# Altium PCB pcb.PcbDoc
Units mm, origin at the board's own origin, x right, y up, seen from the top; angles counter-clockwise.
Board outline 64.9 x 47.24 mm, 2 copper layers (Top Layer, Bottom Layer); 18 components, 15 nets, 54 pads, 4 vias.
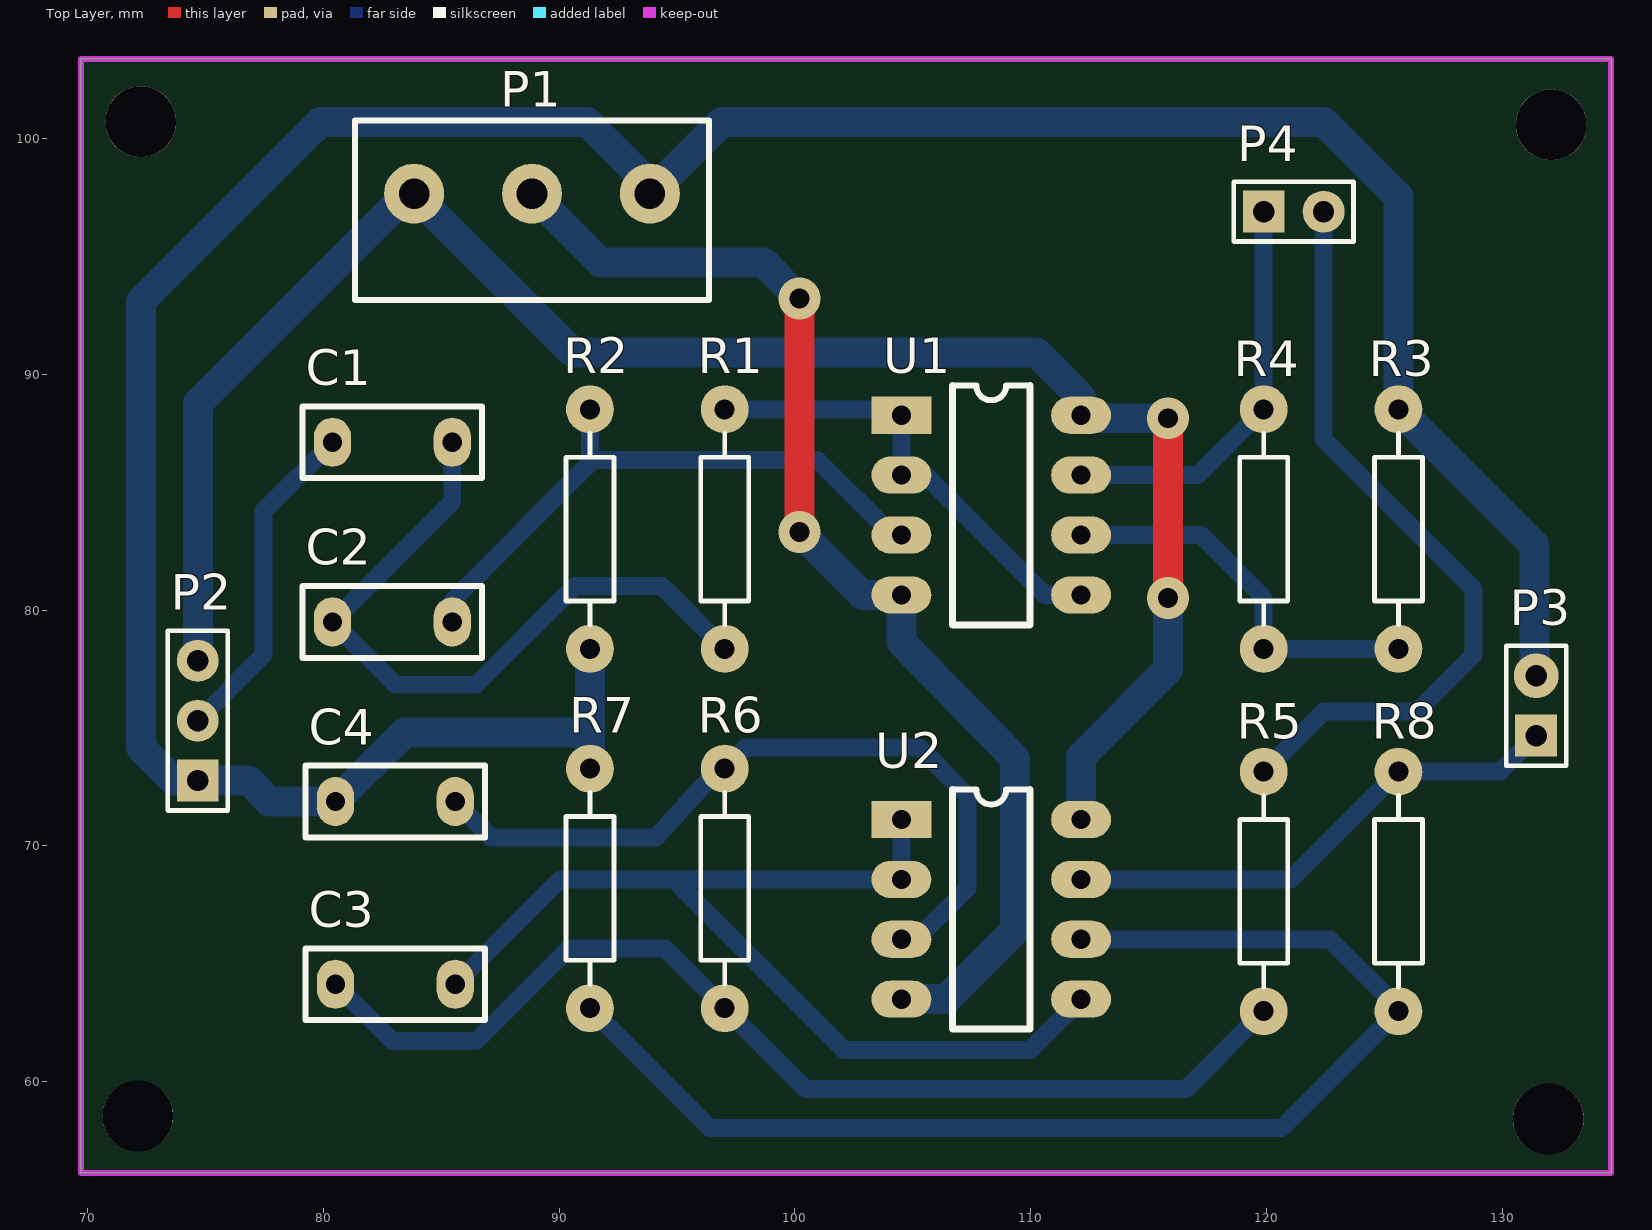
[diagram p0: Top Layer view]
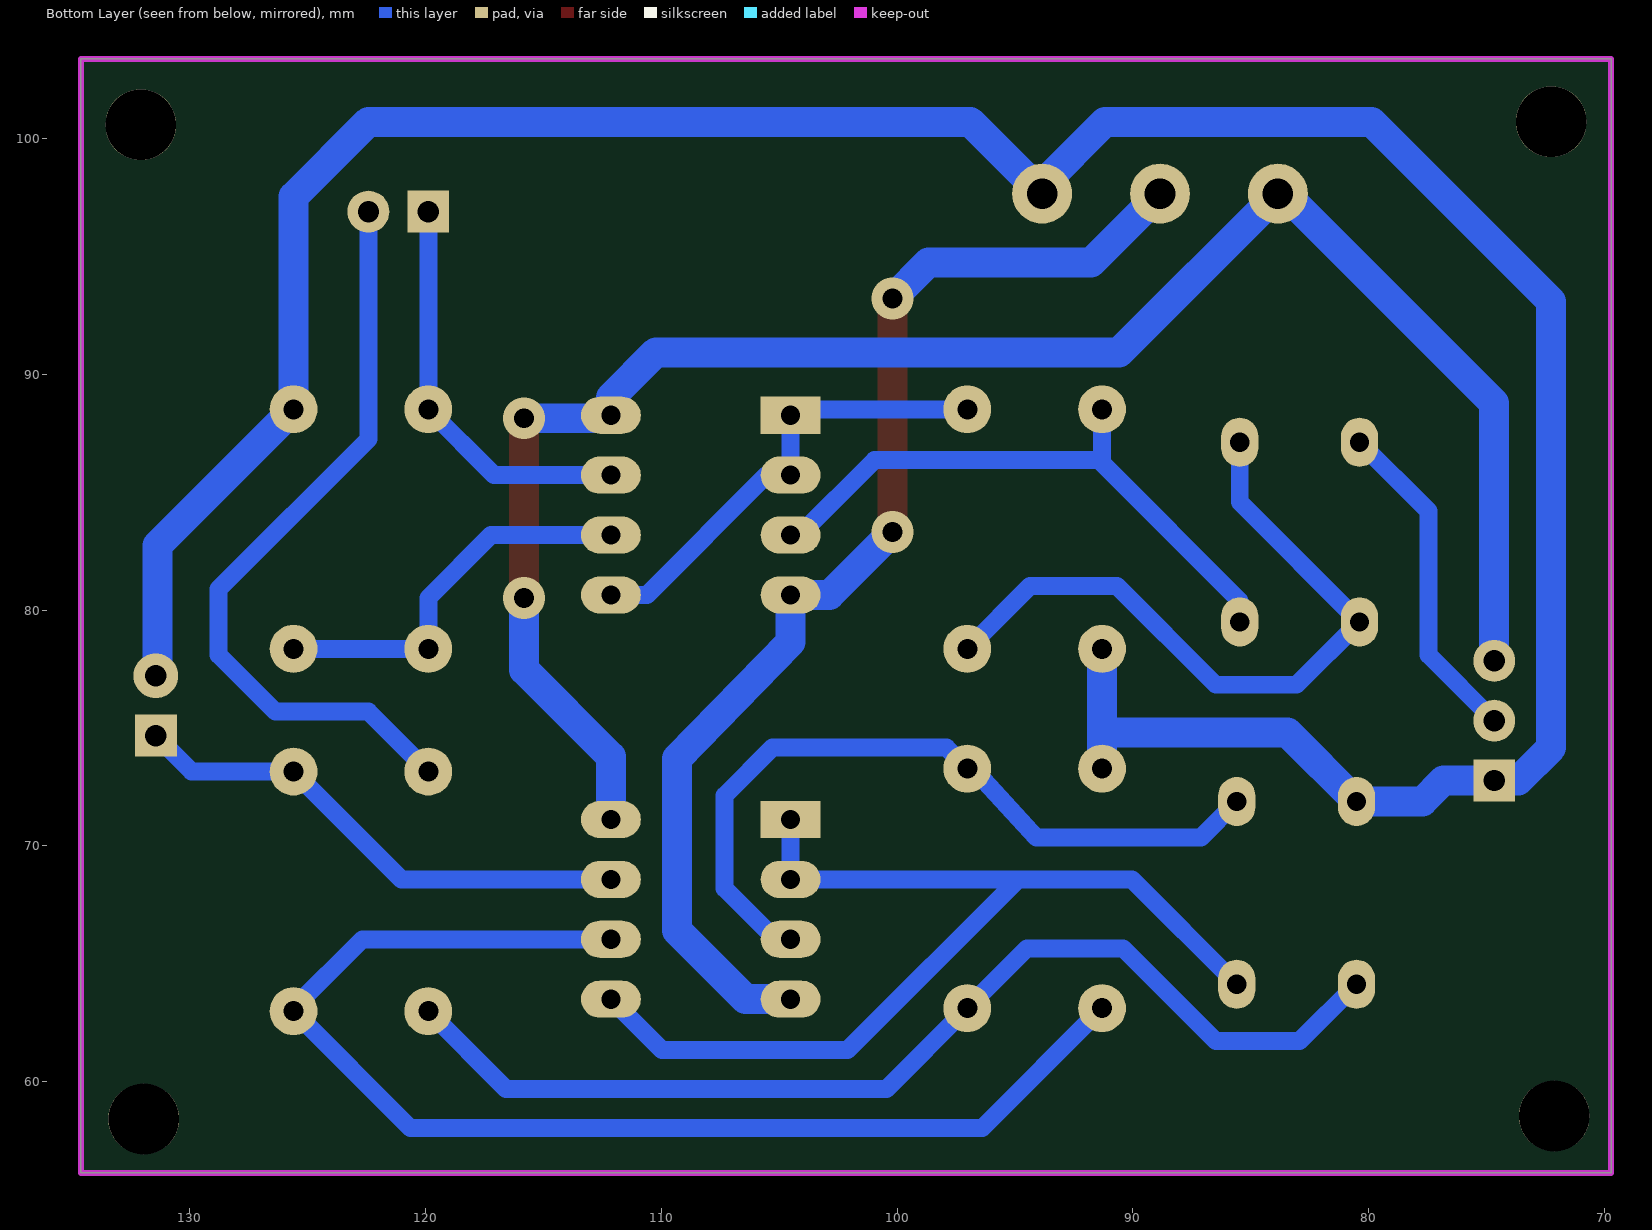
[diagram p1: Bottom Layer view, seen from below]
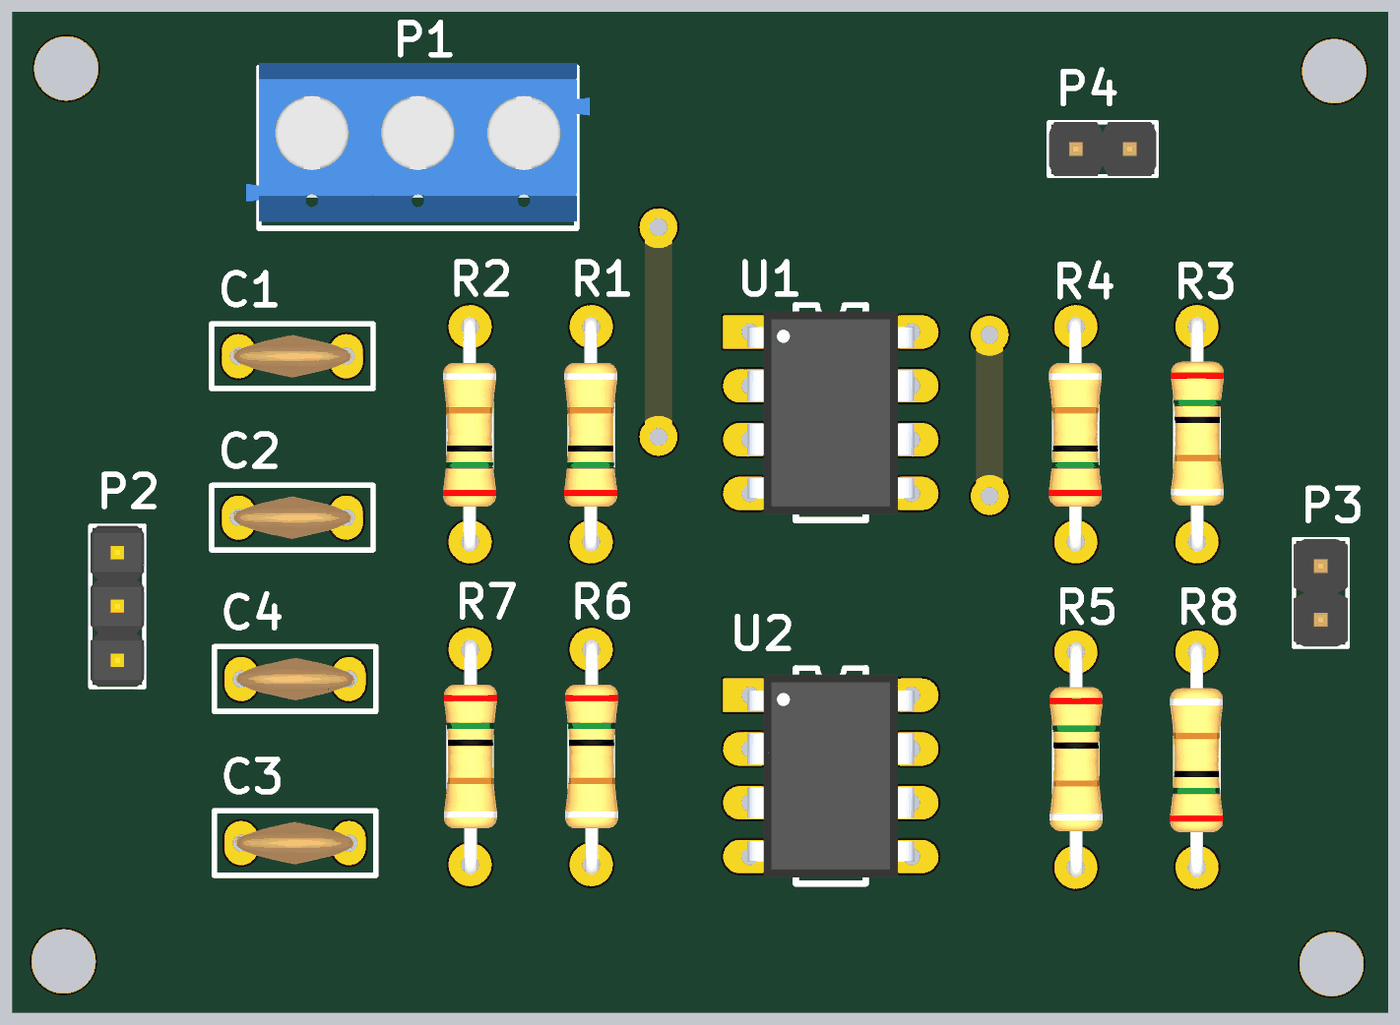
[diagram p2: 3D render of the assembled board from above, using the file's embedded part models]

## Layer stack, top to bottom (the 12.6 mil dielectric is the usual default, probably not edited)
Top Solder: solder mask 0.0102, Solder Resist, Dk 3.5
Top Layer: signal copper 0.0356
Dielectric 1: dielectric 0.32, FR-4, Dk 4.8
Bottom Layer: signal copper 0.0356
Bottom Solder: solder mask 0.0102, Solder Resist, Dk 3.5

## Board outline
69.723,56.134 69.723,103.378 134.62,103.378 134.62,56.134

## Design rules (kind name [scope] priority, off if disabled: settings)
Clearance [All] p1: gap=0.381 ignorepadtopadclearanceinfootprint=FALSE
PolygonConnect [All] p1: connectstyle=Relief reliefconductorwidth=0.254 reliefentries=4 polygonreliefangle="90 Angle" airgapwidth=0.254
RoutingVias [All] p1: holewidth=0.711 width=1.27 viastyle="Through Hole" minholewidth=0.711 minwidth=1.27 maxholewidth=0.711 maxwidth=1.27
SolderMaskExpansion [All] p1: expansion=0.102
Width Width_1 [InNetClass('Power Class')] p1: maxlimit=1.27 minlimit=1.27 preferedwidth=1.27
Width Width_2 [InNetClass('Signal Class')] p2: maxlimit=0.762 minlimit=0.762 preferedwidth=0.762
30 further rules are at their usual default settings.

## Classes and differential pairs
net class "Signal Class": HP_in HP_out LP_in LP_out NetC1_1 NetC2_1 NetC3_1 NetC3_2 NetC4_2 NetR1_1 NetR3_1 NetR7_1
net class "Power Class": -VCC GND VCC
component class Sema_BCG_2: C1 C2 C4 P1 P2 P3 P4 R1 R2 R3 R4 R5 R6 R7 R8 U1 U2

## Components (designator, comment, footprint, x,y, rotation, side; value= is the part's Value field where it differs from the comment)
C1 "Cap" CAP200 85.471,87.122 r180 top value=10uF
C2 "Cap" CAP200 85.471,79.502 r180 top value=10uF
C3 "Cap" CAP200 85.598,64.135 r180 top value=100nF
C4 "Cap" CAP200 80.518,71.882 r0 top value=100nF
P1 "POWER" DG301-5.0 88.853,97.663 r180 top
P2 "Signal IN (ACCEL)" HDR1X3 74.676,75.311 r180 top
P3 "Signal OUT (DAQ)" HDR1X2#1 131.445,74.676 r90 top
P4 "FILT" HDR1X2#2 119.888,96.901 r0 top
R1 "Res1" AXIAL-0.4 97.028,83.439 r270 top value=10K
R2 "Res1" AXIAL-0.4 91.313,83.439 r270 top value=10K
R3 "Res1" AXIAL-0.4 125.603,83.439 r90 top value=2k7
R4 "Res1" AXIAL-0.4 119.888,83.439 r270 top value=47K
R5 "Res1" AXIAL-0.4 119.888,68.072 r90 top value=100K
R6 "Res1" AXIAL-0.4 97.028,68.199 r90 top value=100K
R7 "Res1" AXIAL-0.4 91.313,68.199 r90 top value=47k
R8 "Res1" AXIAL-0.4 125.603,68.072 r270 top value=100k
U1 "TL072" DIP-8 104.521,88.265 r0 top
U2 "TL072" DIP-8 104.521,71.12 r0 top

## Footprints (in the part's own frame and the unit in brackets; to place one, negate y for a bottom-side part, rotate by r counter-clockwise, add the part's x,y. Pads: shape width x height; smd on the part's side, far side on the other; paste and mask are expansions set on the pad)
AXIAL-0.4 [mil] "Axial Device, Thru-Hole; 2 Leads; 0.4 in Pin Spacing"
  round 80 hole 33.46: 1(-200,0) 2(200,0)
  silkscreen extent -160,-40 160,40, body extent -219,-50 219,48, height 146
CAP200 [mil]
  oval 62x82 hole 32: 1(0,0) 2(200,0)
  silkscreen extent -50,-60 250,60, body extent -11,-39 210,39, height 246
DG301-5.0 [mm]
  round 2.54 hole 1.3: 1(-5,0) 2(0,0) 3(5,0)
  silkscreen extent -7.5,-3.1 7.5,4.5, body extent -8.1,-3.3 8.1,4.2, height 5
DIP-8 [mil]
  rect 100x62 hole 32: 1(0,0)
  oval 100x62 hole 32: 2(0,-100) 3(0,-200) 4(0,-300) 5(300,-300) 6(300,-200) 7(300,-100) 8(300,0)
  silkscreen extent 85,-350 215,50, body extent -5,-339 305,39, height 200
HDR1X2#1 [mm] "Connector; Header; 2 Position"
  rect 1.778x1.778 hole 0.9: 1(0,0)
  round 1.905 hole 0.9: 2(2.54,0)
  silkscreen extent -1.27,-1.27 3.81,1.27, body extent -1.27,-1.27 3.81,1.27, height 8.79
HDR1X2#2 [mm] "Connector; Header; 2 Position"
  rect 1.778x1.778 hole 0.9: 1(0,0)
  round 1.778 hole 0.9: 2(2.54,0)
  silkscreen extent -1.27,-1.27 3.81,1.27, body extent -1.27,-1.27 3.81,1.27, height 8.79
HDR1X3 [mil]
  rect 70x70 hole 35.43: 1(0,100)
  round 70 hole 35.43: 2(0,0) 3(0,-100)
  silkscreen extent -50,-150 50,150, body extent -50,-150 50,150, height 374

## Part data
C1 C2 C3 C4: "Capacitor"
P1 P2: library part "Header 3", "Header, 3-Pin"
P3 P4: library part "Header 2", "Header, 2-Pin"
R1 R2 R3 R4 R5 R6 R7 R8: "Resistor"
U1 U2: "Dual standard operational amplifier 8-PDIP 0 to 70", Package="PDIP-8 Texas"

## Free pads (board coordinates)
  round 3 hole 3: 0(72.136,58.547) 0(72.263,100.711) 0(131.953,58.42) 0(132.08,100.584)

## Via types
v1: diameter 1.778, hole 0.838, Top Layer to Bottom Layer, 4 vias

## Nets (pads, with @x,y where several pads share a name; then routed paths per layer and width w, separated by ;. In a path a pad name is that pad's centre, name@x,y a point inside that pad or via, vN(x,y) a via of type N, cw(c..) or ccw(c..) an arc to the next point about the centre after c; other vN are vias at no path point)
-VCC: P1.2 U1.4 U2.4 | length 51.1
  Top Layer w1.27: v1@100.076,83.439 v1(100.203,83.312) v1(100.203,93.218)
  Bottom Layer w1.27: P1.2 91.774,94.742 98.679,94.742 v1(100.203,93.218) v1@100.33,93.091 ; v1(100.203,83.312) 102.87,80.645 U1.4 104.521,78.645 109.347,73.698 109.347,66.421 106.426,63.5 U2.4
GND: C4.1 P1.1 P2.1 P3.2 R2.2 R3.2 R7.2 | length 128.9
  Bottom Layer w1.27: R7.2@91.059,73.533 R7.2 91.313,75.057 ; R2.2 91.313,75.057 ; P3.2@131.381,77.279 131.381,82.74 R3.2 125.603,97.536 122.428,100.711 96.901,100.711 P1.1 93.853,98.044 91.186,100.711 79.883,100.711 72.263,93.091 72.263,74.168 73.66,72.771 P2.1 76.835,72.771 77.724,71.882 C4.1 83.439,74.803 91.059,74.803 91.313,75.057
HP_in: C1.2 P2.2 | length 14.6
  Bottom Layer w0.762: P2.2@75.057,75.311 P2.2 77.47,78.105 77.47,84.201 C1.2
HP_out: P4.1 R4.1 U1.7 | length 17.3
  Bottom Layer w0.762: U1.7 117.094,85.725 R4.1 P4.1
LP_in: P4.2 R5.2 | length 32.4
  Bottom Layer w0.762: R5.2 122.428,75.692 126.365,75.692 128.778,78.105 128.778,80.899 122.428,87.249 P4.2
LP_out: P3.1 R8.1 U2.7 | length 21.8
  Bottom Layer w0.762: U2.7 121.031,68.58 R8.1 129.921,73.152 P3.1
NetC1_1: C1.1 C2.2 R1.2 | length 30.3
  Bottom Layer w0.762: C1.1 85.471,84.582 C2.2 83.058,76.835 86.487,76.835 90.678,81.026 94.361,81.026 R1.2
NetC2_1: C2.1 R2.1 U1.3 | length 26
  Bottom Layer w0.762: C2.1 85.471,80.391 91.313,86.233 ; R2.1 91.313,86.233 ; U1.3 104.14,83.185 100.965,86.36 91.44,86.36 91.313,86.233
NetC3_1: C3.1 U2.1 U2.2 U2.5 | length 44.5
  Bottom Layer w0.762: C3.1 90.043,68.58 94.869,68.58 ; U2.1 U2.2 94.869,68.58 ; U2.5 109.982,61.341 102.108,61.341 94.869,68.58
NetC3_2: C3.2 R5.1 R6.1 | length 45.8
  Bottom Layer w0.762: C3.2 82.931,61.722 86.487,61.722 90.424,65.659 94.488,65.659 R6.1 100.457,59.69 116.586,59.69 R5.1
NetC4_2: C4.2 R6.2 U2.3 | length 33
  Bottom Layer w0.762: C4.2 87.122,70.358 94.096,70.358 96.774,73.279 R6.2 97.917,74.168 105.283,74.168 107.315,72.136 107.315,68.199 105.156,66.04 U2.3 U2.3@104.013,66.04
NetR1_1: R1.1 U1.1 U1.2 U1.5 | length 19.9
  Bottom Layer w0.762: R1.1 104.267,88.519 U1.1 U1.2 105.537,85.725 110.617,80.645 U1.5
NetR3_1: R3.1 R4.2 U1.6 | length 16.7
  Bottom Layer w0.762: U1.6 117.221,83.185 119.888,80.518 R4.2 R3.1
NetR7_1: R7.1 R8.2 U2.6 | length 53.2
  Bottom Layer w0.762: R7.1 96.393,58.039 120.65,58.039 R8.2 125.603,63.119 122.682,66.04 U2.6
VCC: P1.3 P2.3 U1.8 U2.8 | length 78.7
  Top Layer w1.27: v1(115.824,80.518) v1(115.824,88.138)
  Bottom Layer w1.27: P2.3 74.693,77.868 74.693,88.79 83.566,97.663 P1.3 90.584,90.932 110.236,90.932 112.141,89.027 U1.8 112.268,88.138 v1(115.824,88.138) ; U2.8 112.141,73.787 115.824,77.47 v1(115.824,80.518)

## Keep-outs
Keep-Out Layer:
  the board outline again, w0.254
